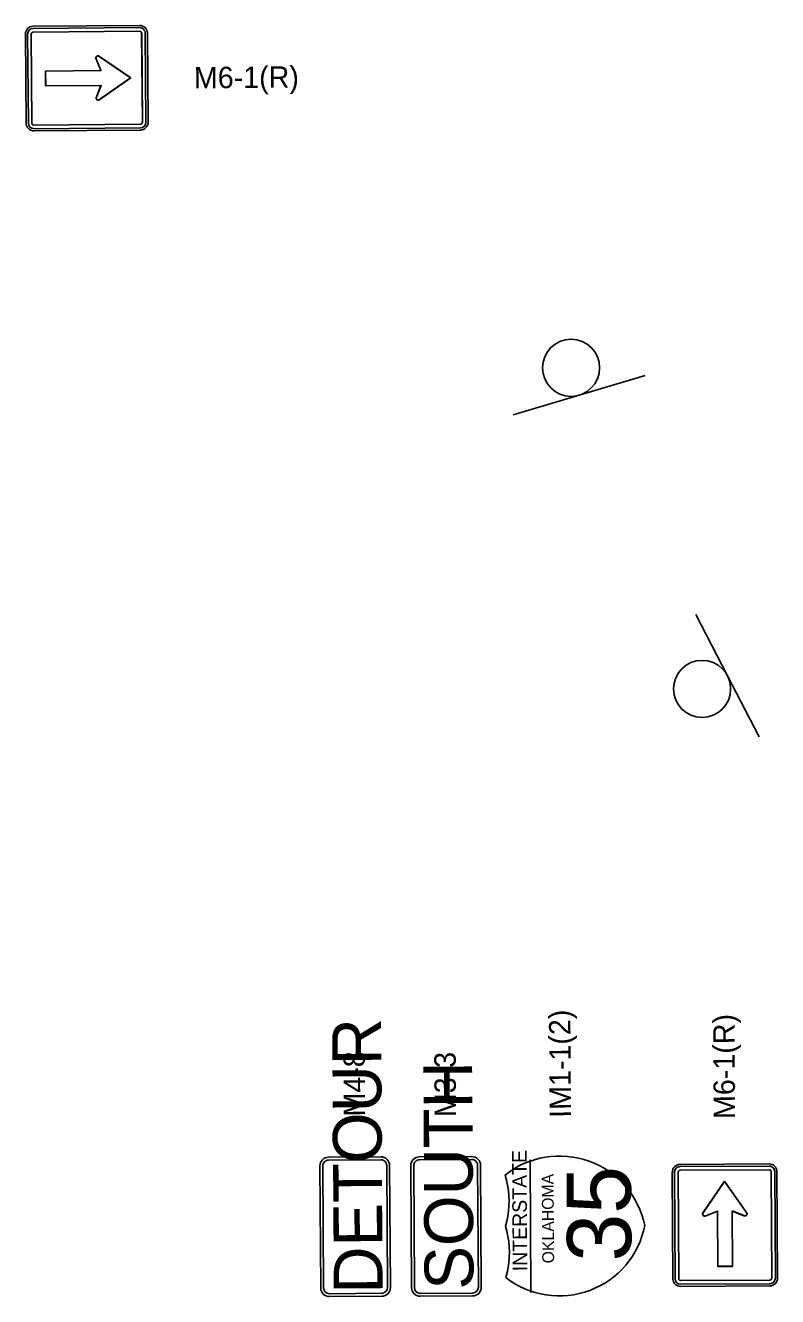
# Model space of a CAD drawing. Extents: x 2135767 to 2151731, y 141839 to 175894.
# Drawn here: x 2149001.9 to 2149212.6, y 145257 to 145613.3 of the extents above; entities that cross this region are included whole.
import ezdxf

# ---------------------------------------------------------------- set-up
doc = ezdxf.new("R2010")
doc.units = 0
doc.layers.add('PR_Phasing_Detour_1', color=7, linetype='Continuous')

msp = doc.modelspace()

# ---------------------------------------------------------------- linework, layer by layer
at = {"layer": 'PR_Phasing_Detour_1'}
for p, q in [((2149033.89, 145613.27), (2149004.03, 145613.03)), ((2149033.9, 145612.66), (2149004.04, 145612.42)), ((2149033.9, 145612.66), (2149004.04, 145612.42)), ((2149004.05, 145611.4), (2149033.9, 145611.64)), ((2149004.05, 145611.4), (2149033.9, 145611.64)), ((2149001.89, 145610.85), (2149002.09, 145585.87)), ((2149002.5, 145610.85), (2149002.7, 145585.88)), ((2149002.5, 145610.85), (2149002.7, 145585.88)), ((2149003.71, 145585.88), (2149003.51, 145610.86)), ((2149003.72, 145585.88), (2149003.51, 145610.86)), ((2149034.44, 145611.11), (2149034.65, 145586.13)), ((2149034.45, 145611.11), (2149034.65, 145586.13)), ((2149035.66, 145586.14), (2149035.46, 145611.12)), ((2149035.66, 145586.14), (2149035.46, 145611.12)), ((2149036.27, 145586.15), (2149036.07, 145611.12)), ((2149031.32, 145598.59), (2149022.25, 145604.76)), ((2149021.57, 145604.06), (2149022.98, 145600.61)), ((2149022.98, 145600.61), (2149007.5, 145600.48)), ((2149007.5, 145600.48), (2149007.53, 145596.32)), ((2149022.35, 145592.28), (2149031.32, 145598.59)), ((2149007.53, 145596.32), (2149023.01, 145596.44)), ((2149023.01, 145596.44), (2149021.66, 145592.96)), ((2149034.11, 145585.59), (2149004.26, 145585.35)), ((2149034.11, 145585.59), (2149004.26, 145585.35)), ((2149004.26, 145584.33), (2149034.12, 145584.57)), ((2149004.26, 145584.33), (2149034.12, 145584.57)), ((2149004.27, 145583.72), (2149034.13, 145583.96)), ((2149157.01, 145509.65), (2149175.52, 145515.12)), ((2149138.5, 145504.18), (2149157.01, 145509.65)), ((2149198.55, 145431.01), (2149189.68, 145448.15)), ((2149207.43, 145413.87), (2149198.55, 145431.01)), ((2149101.47, 145296.2), (2149086.81, 145296.11)), ((2149101.47, 145295.39), (2149086.82, 145295.3)), ((2149126.92, 145296.29), (2149112.27, 145296.2)), ((2149126.93, 145295.47), (2149112.28, 145295.38)), ((2149143.52, 145258.2), (2149143.29, 145295.39)), ((2149084.39, 145293.65), (2149084.6, 145259.47)), ((2149085.2, 145293.66), (2149085.41, 145259.47)), ((2149103.32, 145259.58), (2149103.11, 145293.77)), ((2149104.13, 145259.59), (2149103.92, 145293.78)), ((2149109.84, 145293.74), (2149110.06, 145259.55)), ((2149110.66, 145293.74), (2149110.87, 145259.56)), ((2149128.78, 145259.67), (2149128.57, 145293.86)), ((2149129.59, 145259.67), (2149129.38, 145293.86)), ((2149183.11, 145291.88), (2149183.3, 145262.02)), ((2149183.72, 145291.89), (2149183.91, 145262.03)), ((2149183.72, 145291.89), (2149183.91, 145262.03)), ((2149184.93, 145262.03), (2149184.74, 145291.89)), ((2149184.93, 145262.03), (2149184.74, 145291.89)), ((2149210.24, 145294.22), (2149185.26, 145294.06)), ((2149210.24, 145293.61), (2149185.27, 145293.45)), ((2149210.24, 145293.61), (2149185.27, 145293.45)), ((2149185.27, 145292.43), (2149210.25, 145292.59)), ((2149185.27, 145292.43), (2149210.25, 145292.59)), ((2149210.79, 145292.05), (2149210.97, 145262.2)), ((2149210.79, 145292.05), (2149210.97, 145262.2)), ((2149211.99, 145262.2), (2149211.81, 145292.06)), ((2149211.99, 145262.2), (2149211.81, 145292.06)), ((2149212.6, 145262.21), (2149212.42, 145292.06)), ((2149197.78, 145289.29), (2149191.59, 145280.23)), ((2149204.08, 145280.31), (2149197.78, 145289.29)), ((2149192.29, 145279.54), (2149195.75, 145280.95)), ((2149195.75, 145280.95), (2149195.85, 145265.47)), ((2149200.01, 145265.49), (2149199.92, 145280.98)), ((2149199.92, 145280.98), (2149203.39, 145279.61)), ((2149195.85, 145265.47), (2149200.01, 145265.49)), ((2149210.44, 145261.66), (2149185.46, 145261.5)), ((2149210.44, 145261.66), (2149185.46, 145261.5)), ((2149185.47, 145260.48), (2149210.45, 145260.64)), ((2149185.47, 145260.48), (2149210.45, 145260.64)), ((2149185.48, 145259.87), (2149210.45, 145260.03)), ((2149087.05, 145257.85), (2149101.7, 145257.95)), ((2149087.06, 145257.04), (2149101.71, 145257.13)), ((2149112.51, 145257.94), (2149127.16, 145258.03)), ((2149112.51, 145257.12), (2149127.16, 145257.22))]:
    msp.add_line(p, q, dxfattribs=at)
for points in [[(2149031.38, 145598.59), (2149022.31, 145604.77)], [(2149021.62, 145604.07), (2149023.03, 145600.61), (2149007.55, 145600.48), (2149007.58, 145596.32), (2149023.07, 145596.45), (2149021.71, 145592.97)], [(2149022.41, 145592.28), (2149031.38, 145598.59)], [(2149136.43, 145262.38), (2149137.69, 145261.46), (2149139, 145260.63), (2149140.37, 145259.88), (2149141.78, 145259.22), (2149143.22, 145258.65), (2149144.71, 145258.17), (2149146.22, 145257.79), (2149147.75, 145257.5), (2149149.29, 145257.32), (2149150.85, 145257.23), (2149152.4, 145257.24), (2149153.96, 145257.35), (2149155.5, 145257.56), (2149157.03, 145257.87), (2149158.53, 145258.27), (2149160, 145258.77), (2149161.44, 145259.37), (2149162.84, 145260.05), (2149164.2, 145260.82), (2149165.5, 145261.67), (2149166.74, 145262.61), (2149167.92, 145263.62), (2149169.04, 145264.71), (2149170.08, 145265.87), (2149171.05, 145267.09), (2149171.94, 145268.37), (2149172.74, 145269.7), (2149173.46, 145271.08), (2149174.09, 145272.51), (2149174.62, 145273.97), (2149175.07, 145275.46), (2149175.41, 145276.98), (2149175.05, 145278.49), (2149174.59, 145279.98), (2149174.03, 145281.43), (2149173.39, 145282.85), (2149172.65, 145284.22), (2149171.83, 145285.55), (2149170.93, 145286.81), (2149169.94, 145288.02), (2149168.89, 145289.17), (2149167.76, 145290.24), (2149166.56, 145291.24), (2149165.31, 145292.16), (2149164, 145293), (2149162.63, 145293.75), (2149161.23, 145294.42), (2149159.78, 145294.99), (2149158.3, 145295.47), (2149156.79, 145295.86), (2149155.26, 145296.15), (2149153.72, 145296.34), (2149152.16, 145296.43), (2149150.6, 145296.42), (2149149.05, 145296.31), (2149147.51, 145296.11), (2149145.98, 145295.8), (2149144.48, 145295.4), (2149143, 145294.91), (2149141.56, 145294.32), (2149140.16, 145293.64), (2149138.8, 145292.87), (2149137.5, 145292.02), (2149136.25, 145291.09), (2149136.65, 145289.69), (2149136.96, 145288.26), (2149137.18, 145286.83), (2149137.32, 145285.38), (2149137.37, 145283.92), (2149137.34, 145282.46), (2149137.22, 145281.01), (2149137.01, 145279.57), (2149136.72, 145278.14), (2149136.34, 145276.74), (2149136.74, 145275.33), (2149137.05, 145273.91), (2149137.27, 145272.47), (2149137.41, 145271.02), (2149137.46, 145269.57), (2149137.43, 145268.11), (2149137.31, 145266.66), (2149137.1, 145265.22), (2149136.81, 145263.79), (2149136.43, 145262.38)], [(2149197.78, 145289.34), (2149191.59, 145280.28)], [(2149204.08, 145280.36), (2149197.78, 145289.34)], [(2149192.29, 145279.59), (2149195.75, 145281), (2149195.85, 145265.52), (2149200.01, 145265.54), (2149199.91, 145281.03), (2149203.39, 145279.66)]]:
    msp.add_lwpolyline(points, dxfattribs=at)
for centre in [(2149154.75, 145517.32), (2149191.45, 145427.33)]:
    msp.add_circle(centre, 8, dxfattribs=at)
for centre, radius, start, end in [((2149004.05, 145610.86), 2.16, 90.4611, 180.4611), ((2149004.05, 145610.86), 1.55, 90.4611, 180.4611), ((2149004.05, 145610.86), 1.55, 90.4611, 180.4611), ((2149033.91, 145611.1), 2.16, 0.4611, 90.4611), ((2149033.91, 145611.1), 1.55, 0.4611, 90.4611), ((2149033.91, 145611.1), 1.55, 0.4611, 90.4611), ((2149033.91, 145611.1), 0.537, 0.4611, 90.4611), ((2149033.91, 145611.1), 0.537, 0.4611, 90.4611), ((2149004.05, 145610.86), 0.537, 90.4611, 180.4611), ((2149004.05, 145610.86), 0.537, 90.4611, 180.4611), ((2149022.26, 145604.07), 0.694, 90.4611, 180.4611), ((2149022.31, 145604.07), 0.694, 90.4611, 180.4611), ((2149022.35, 145592.97), 0.694, 180.4611, 270.4611), ((2149022.4, 145592.97), 0.694, 180.4611, 270.4611), ((2149004.25, 145585.89), 2.16, 180.4611, 270.4611), ((2149004.25, 145585.89), 1.55, 180.4611, 270.4611), ((2149004.25, 145585.89), 1.55, 180.4611, 270.4611), ((2149004.25, 145585.89), 0.537, 180.4611, 270.4611), ((2149004.25, 145585.89), 0.537, 180.4611, 270.4611), ((2149034.11, 145586.13), 0.537, 270.4611, 0.4611), ((2149034.11, 145586.13), 0.537, 270.4611, 0.4611), ((2149034.11, 145586.13), 1.55, 270.4611, 0.4611), ((2149034.11, 145586.13), 1.55, 270.4611, 0.4611), ((2149034.11, 145586.13), 2.16, 270.4611, 0.4611), ((2149086.83, 145293.67), 2.44, 90.3555, 180.3555), ((2149086.83, 145293.67), 1.63, 90.3555, 180.3555), ((2149101.48, 145293.76), 2.44, 0.3555, 90.3555), ((2149101.48, 145293.76), 1.63, 0.3555, 90.3555), ((2149112.29, 145293.75), 2.44, 90.3555, 180.3555), ((2149112.29, 145293.75), 1.63, 90.3555, 180.3555), ((2149126.94, 145293.84), 2.44, 0.3555, 90.3555), ((2149126.94, 145293.84), 1.63, 0.3555, 90.3555), ((2149185.28, 145291.9), 2.16, 90.3555, 180.3555), ((2149185.28, 145291.9), 1.55, 90.3555, 180.3555), ((2149185.28, 145291.9), 1.55, 90.3555, 180.3555), ((2149185.28, 145291.9), 0.537, 90.3555, 180.3555), ((2149185.28, 145291.9), 0.537, 90.3555, 180.3555), ((2149210.25, 145292.05), 2.16, 0.3555, 90.3555), ((2149210.25, 145292.05), 1.55, 0.3555, 90.3555), ((2149210.25, 145292.05), 1.55, 0.3555, 90.3555), ((2149210.25, 145292.05), 0.537, 0.3555, 90.3555), ((2149210.25, 145292.05), 0.537, 0.3555, 90.3555), ((2149192.29, 145280.29), 0.694, 180.3555, 270.3555), ((2149192.29, 145280.23), 0.694, 180.3555, 270.3555), ((2149203.39, 145280.36), 0.694, 270.3555, 0.3555), ((2149203.39, 145280.3), 0.694, 270.3555, 0.3555), ((2149087.04, 145259.48), 2.44, 180.3555, 270.3555), ((2149087.04, 145259.48), 1.63, 180.3555, 270.3555), ((2149101.69, 145259.57), 1.63, 270.3555, 0.3555), ((2149101.69, 145259.57), 2.44, 270.3555, 0.3555), ((2149112.5, 145259.57), 2.44, 180.3555, 270.3555), ((2149112.5, 145259.57), 1.63, 180.3555, 270.3555), ((2149127.15, 145259.66), 1.63, 270.3555, 0.3555), ((2149127.15, 145259.66), 2.44, 270.3555, 0.3555), ((2149185.46, 145262.04), 2.16, 180.3555, 270.3555), ((2149185.46, 145262.04), 1.55, 180.3555, 270.3555), ((2149185.46, 145262.04), 1.55, 180.3555, 270.3555), ((2149185.46, 145262.04), 0.537, 180.3555, 270.3555), ((2149185.46, 145262.04), 0.537, 180.3555, 270.3555), ((2149210.44, 145262.19), 0.537, 270.3555, 0.3555), ((2149210.44, 145262.19), 0.537, 270.3555, 0.3555), ((2149210.44, 145262.19), 2.16, 270.3555, 0.3555), ((2149210.44, 145262.19), 1.55, 270.3555, 0.3555), ((2149210.44, 145262.19), 1.55, 270.3555, 0.3555)]:
    msp.add_arc(centre, radius, start, end, dxfattribs=at)

# ---------------------------------------------------------------- texts
for s, height, rotation, p in [('M6-1(R)', 6, 0.4611, (2149049.1, 145595.61)), ('DETOUR', 13.675, 90.3555, (2149101.97, 145257.9)), ('IM1-1(2)', 6, 90.3555, (2149154.74, 145307.15)), ('M6-1(R)', 6, 90.3555, (2149200.71, 145306.83)), ('M4-8', 6, 90.3555, (2149097.07, 145307.51)), ('M3-3', 6, 90.3555, (2149122.53, 145307.35)), ('SOUTH', 13.675, 90.3555, (2149127.42, 145259.02)), ('INTERSTATE', 4.084, 90.3555, (2149142.49, 145264.14)), ('OKLAHOMA', 3.31, 90.3555, (2149150, 145266.36)), ('35', 17.974, 90.3555, (2149171.63, 145266.91))]:
    msp.add_text(s, height=height, rotation=rotation, dxfattribs=at).set_placement(p)

doc.saveas('drawing.dxf')
